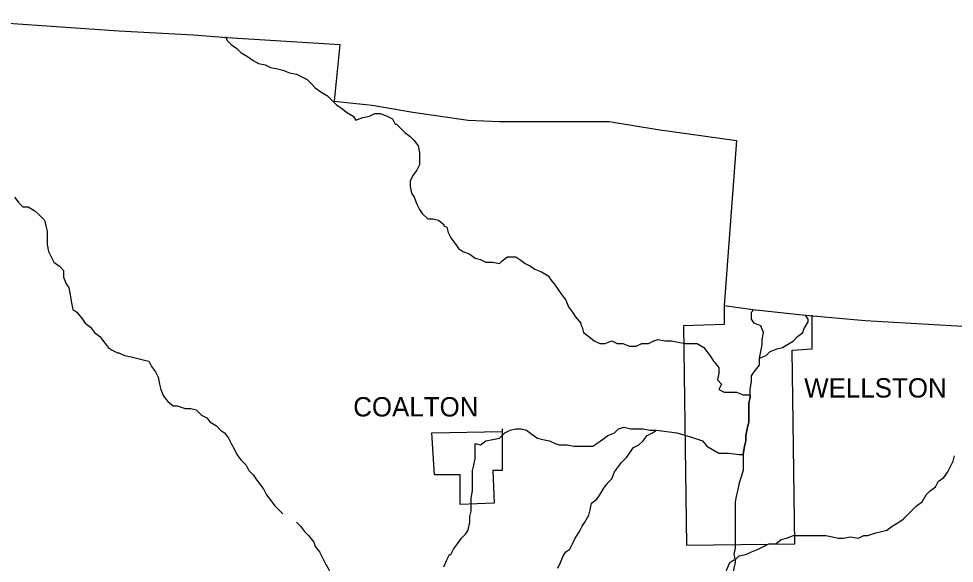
# Model space of a CAD drawing. Extents: x 0 to 34, y 0 to 22.
# Drawn here: x 6.966 to 7.908, y 18.061 to 18.609 of the extents above; entities that cross this region are included whole.
import ezdxf

# ---------------------------------------------------------------- set-up
doc = ezdxf.new("R2010")
doc.units = 0
doc.layers.add('Default', color=7, linetype='Continuous')

msp = doc.modelspace()

# ---------------------------------------------------------------- linework, layer by layer
at = {"layer": 'Default'}
for points in [[(6.89248, 18.60931), (7.067, 18.59704), (7.14199, 18.59295), (7.17607, 18.59022), (7.28924, 18.58341), (7.28378, 18.52614), (7.32196, 18.52205), (7.36286, 18.51524), (7.41876, 18.50705), (7.45012, 18.50569), (7.50738, 18.50569), (7.56056, 18.50569), (7.60964, 18.49751), (7.68872, 18.4866), (7.67645, 18.32027)], [(7.17607, 18.59022), (7.17471, 18.59022), (7.17607, 18.5875), (7.18016, 18.58341), (7.18562, 18.57932), (7.18971, 18.57523), (7.19652, 18.57114), (7.20198, 18.56705), (7.20743, 18.56432), (7.21425, 18.56295), (7.2197, 18.56023), (7.22652, 18.55886), (7.23197, 18.5575), (7.23879, 18.55477), (7.24561, 18.55341), (7.25106, 18.55068), (7.25651, 18.54796), (7.2606, 18.54387), (7.26469, 18.53978), (7.27015, 18.53569), (7.27697, 18.5316), (7.28106, 18.52751), (7.28651, 18.52205), (7.2906, 18.51933), (7.29605, 18.51524), (7.30287, 18.51114), (7.3056, 18.50705), (7.31241, 18.50978), (7.31923, 18.51114), (7.32468, 18.51387), (7.33014, 18.51387), (7.33696, 18.51114), (7.34241, 18.50842), (7.34514, 18.50296)], [(7.34514, 18.50296), (7.3465, 18.50296), (7.3465, 18.50296), (7.35059, 18.49887), (7.35468, 18.49478), (7.36013, 18.49069), (7.36422, 18.4866), (7.36831, 18.48115), (7.36968, 18.47433), (7.36968, 18.46888), (7.36968, 18.46206), (7.36695, 18.45661), (7.36286, 18.45115), (7.36013, 18.4457), (7.36013, 18.44025), (7.3615, 18.43343), (7.36422, 18.42934), (7.36695, 18.42252), (7.36968, 18.41707), (7.3724, 18.41298), (7.37786, 18.40752), (7.38331, 18.40752), (7.38877, 18.40616), (7.39422, 18.40207)], [(6.96201, 18.42934), (6.96611, 18.42389), (6.9702, 18.4198), (6.97565, 18.4198), (6.97565, 18.4198)], [(6.97565, 18.4198), (6.98247, 18.41571), (6.98656, 18.41162), (6.99201, 18.40616), (6.99337, 18.40071), (6.99474, 18.39525), (6.99474, 18.38844), (6.99474, 18.38162), (6.9961, 18.3748), (6.99883, 18.36935), (7.00155, 18.3639), (7.00701, 18.35981), (7.0111, 18.35571), (7.0111, 18.3489), (7.01382, 18.34208), (7.01655, 18.33799), (7.01792, 18.33117), (7.01928, 18.32299), (7.02064, 18.31618), (7.02473, 18.31345), (7.03019, 18.30663), (7.03291, 18.30254), (7.03837, 18.29845), (7.04246, 18.293), (7.04791, 18.28891), (7.052, 18.28345), (7.05609, 18.278), (7.06018, 18.27527), (7.06563, 18.27255), (7.06563, 18.27255), (7.067, 18.27255)], [(7.39422, 18.40207), (7.39422, 18.40071), (7.39422, 18.40071), (7.39695, 18.39934), (7.39831, 18.39389), (7.40104, 18.38844), (7.40513, 18.38298), (7.40922, 18.37753), (7.41331, 18.3748), (7.42012, 18.37208), (7.42558, 18.36799), (7.43103, 18.36662), (7.43649, 18.3639), (7.4433, 18.3639), (7.45012, 18.36253), (7.45285, 18.36526), (7.4583, 18.36935), (7.46648, 18.36935), (7.47057, 18.36662), (7.47602, 18.36253), (7.48148, 18.35981), (7.48557, 18.35708), (7.49239, 18.35435), (7.4992, 18.35026), (7.50193, 18.34617), (7.50602, 18.34072), (7.50875, 18.33663), (7.51284, 18.33117), (7.51693, 18.32572), (7.51965, 18.3189), (7.52374, 18.31345), (7.52647, 18.30936), (7.53192, 18.30254)], [(7.67645, 18.32027), (7.67645, 18.30118), (7.63554, 18.29981), (7.63827, 18.07894), (7.74735, 18.0803), (7.74462, 18.27527), (7.76507, 18.27664), (7.76507, 18.31072)], [(7.67645, 18.32027), (7.70508, 18.31618), (7.75825, 18.31072), (7.81824, 18.30527), (7.95731, 18.29709), (8.08411, 18.29163)], [(7.7119, 18.26709), (7.71326, 18.27391), (7.71462, 18.28073), (7.71462, 18.28618), (7.71599, 18.293), (7.71326, 18.29981), (7.70644, 18.30254), (7.70372, 18.30663), (7.70372, 18.31345), (7.70508, 18.31481), (7.70508, 18.31618)], [(7.7119, 18.26709), (7.71871, 18.26982), (7.7228, 18.27391), (7.72962, 18.27664), (7.73507, 18.278), (7.74189, 18.28209), (7.74598, 18.28482), (7.75007, 18.28891), (7.75553, 18.293), (7.75689, 18.29709), (7.76098, 18.3039), (7.76098, 18.30663), (7.75825, 18.31072)], [(7.53192, 18.30254), (7.53192, 18.30118), (7.53329, 18.29845), (7.53465, 18.293), (7.54011, 18.28891), (7.54556, 18.28482), (7.55101, 18.28209), (7.55647, 18.28209), (7.56328, 18.28482), (7.56874, 18.28209), (7.57419, 18.28209), (7.58101, 18.27936), (7.58783, 18.27936), (7.59328, 18.28209), (7.6001, 18.28209), (7.60555, 18.28482), (7.60964, 18.28618), (7.61646, 18.28482), (7.62327, 18.28482), (7.63009, 18.28345), (7.63691, 18.28209), (7.64373, 18.28209), (7.64918, 18.28209), (7.656, 18.278), (7.65872, 18.27391), (7.66281, 18.26846), (7.66554, 18.26437)], [(7.067, 18.27255), (7.07245, 18.26982), (7.07927, 18.26846), (7.08472, 18.26709), (7.09154, 18.26573), (7.09699, 18.26437), (7.09972, 18.25891), (7.10381, 18.25346), (7.10654, 18.248), (7.1079, 18.24119), (7.10926, 18.23573), (7.11199, 18.22892), (7.11608, 18.22346), (7.12154, 18.21937), (7.12563, 18.21937), (7.13381, 18.21665), (7.13926, 18.21665), (7.14471, 18.21528), (7.15017, 18.20983), (7.15562, 18.2071), (7.15835, 18.20301), (7.16516, 18.19892), (7.16925, 18.19483), (7.17335, 18.1921)], [(7.66554, 18.26437), (7.6669, 18.263), (7.67099, 18.25755), (7.67099, 18.25209), (7.66963, 18.24528), (7.67372, 18.24119), (7.67099, 18.23573), (7.67645, 18.23301), (7.6819, 18.23301), (7.68872, 18.23301), (7.69554, 18.23028), (7.70235, 18.23028)], [(7.70235, 18.23028), (7.70235, 18.23573), (7.70372, 18.24391), (7.70372, 18.24937), (7.70644, 18.25346), (7.7119, 18.26028), (7.7119, 18.26573), (7.7119, 18.26709), (7.7119, 18.26709)], [(7.69554, 18.17029), (7.6969, 18.17847), (7.69826, 18.18392), (7.69826, 18.18938), (7.69963, 18.19619), (7.70099, 18.20301), (7.70099, 18.20847), (7.70099, 18.21528), (7.70099, 18.2221), (7.70235, 18.22755), (7.70235, 18.23028)], [(7.70235, 18.23028), (7.70235, 18.22755), (7.70099, 18.2221), (7.70099, 18.21528), (7.70099, 18.20847), (7.70099, 18.20301), (7.69963, 18.19619), (7.69826, 18.18938), (7.69826, 18.18392), (7.6969, 18.17847), (7.69554, 18.17029)], [(7.51147, 18.17983), (7.51829, 18.17983), (7.52511, 18.17847), (7.53192, 18.17847), (7.53874, 18.17847), (7.5442, 18.17847), (7.54829, 18.1812), (7.55374, 18.18529), (7.55919, 18.18938), (7.56601, 18.1921), (7.5701, 18.19619), (7.57555, 18.19756), (7.58237, 18.19619), (7.58919, 18.19619), (7.59464, 18.19619), (7.60146, 18.19483), (7.60828, 18.19483), (7.60828, 18.19483)], [(7.17335, 18.1921), (7.17744, 18.18665), (7.18016, 18.1812), (7.18289, 18.17574), (7.18562, 18.17029), (7.18971, 18.16484), (7.19516, 18.15938), (7.19789, 18.15393), (7.20198, 18.14984), (7.2047, 18.14575), (7.20879, 18.14029), (7.21288, 18.13484), (7.21561, 18.12939), (7.22106, 18.12257), (7.22379, 18.11848), (7.22925, 18.11303), (7.23197, 18.1103), (7.23197, 18.1103)], [(7.45285, 18.19619), (7.45285, 18.15393), (7.4433, 18.15393), (7.44467, 18.12121), (7.41058, 18.11984), (7.41058, 18.14984), (7.38468, 18.14984), (7.38195, 18.1921), (7.45285, 18.19347)], [(7.42558, 18.1812), (7.43103, 18.17983), (7.43649, 18.18392), (7.4433, 18.18529), (7.45012, 18.18665), (7.45557, 18.1921), (7.46103, 18.19483), (7.46648, 18.19619), (7.47193, 18.19619), (7.47739, 18.19483), (7.48284, 18.19074), (7.4883, 18.18665), (7.49375, 18.18529), (7.50057, 18.18392), (7.50602, 18.1812), (7.51011, 18.17983), (7.51147, 18.17983)], [(7.5142, 18.06803), (7.51693, 18.07212), (7.52102, 18.07485), (7.52374, 18.0803), (7.52647, 18.08576), (7.53056, 18.09257), (7.53329, 18.09803), (7.53602, 18.10212), (7.54011, 18.10894), (7.54147, 18.11439), (7.54283, 18.12121), (7.54829, 18.1253), (7.55101, 18.12939), (7.5551, 18.1362), (7.55919, 18.14166), (7.56328, 18.14575), (7.56601, 18.15257), (7.5701, 18.15802), (7.57283, 18.16211), (7.57828, 18.16756), (7.58101, 18.17165), (7.5851, 18.17711), (7.59055, 18.17983), (7.59464, 18.18392), (7.59873, 18.18938), (7.60419, 18.1921), (7.60828, 18.19483), (7.60828, 18.19483)], [(7.60828, 18.19483), (7.62873, 18.1921), (7.64236, 18.18801), (7.65463, 18.18392), (7.65872, 18.17847), (7.67099, 18.17165), (7.68054, 18.17165), (7.69145, 18.17029), (7.69554, 18.17029)], [(7.40104, 18.0694), (7.40376, 18.07485), (7.40785, 18.0803), (7.41194, 18.08576), (7.41603, 18.08985), (7.41876, 18.09394), (7.42012, 18.10212), (7.42012, 18.10757), (7.42149, 18.11303), (7.42149, 18.11984), (7.42149, 18.12666), (7.42285, 18.13348), (7.42285, 18.14029), (7.42285, 18.14575), (7.42285, 18.15393), (7.42421, 18.15938), (7.42558, 18.1662), (7.42558, 18.17165), (7.42558, 18.17847), (7.42558, 18.17983), (7.42558, 18.1812)], [(7.69554, 18.17029), (7.69554, 18.1662), (7.69554, 18.15938), (7.69554, 18.15393), (7.69281, 18.14575), (7.69145, 18.14166), (7.69008, 18.13484), (7.68872, 18.12939), (7.68735, 18.12257), (7.68735, 18.11712), (7.68735, 18.10894), (7.68735, 18.10212), (7.68735, 18.0953), (7.68735, 18.08985), (7.68735, 18.08303), (7.68735, 18.07621), (7.68599, 18.0694), (7.68735, 18.06394)], [(7.80325, 18.08712), (7.81143, 18.08576), (7.81688, 18.08848), (7.82097, 18.08848), (7.82915, 18.09121), (7.8346, 18.09257), (7.84006, 18.09394), (7.84551, 18.09803), (7.85233, 18.10212), (7.85642, 18.10485), (7.86187, 18.1103), (7.86733, 18.11575), (7.87005, 18.11848), (7.87551, 18.12257), (7.8796, 18.12939), (7.88369, 18.13348), (7.88914, 18.13757), (7.89187, 18.14302), (7.89732, 18.14711), (7.90141, 18.15257), (7.90414, 18.15802), (7.90687, 18.16347), (7.90823, 18.16893)], [(7.24561, 18.10212), (7.2497, 18.09803), (7.25379, 18.09257), (7.25788, 18.08848), (7.26333, 18.08167), (7.26469, 18.07758), (7.26878, 18.07212), (7.27151, 18.06667), (7.27424, 18.06122), (7.27833, 18.0544), (7.27969, 18.04895), (7.28378, 18.04349), (7.28651, 18.03667), (7.28787, 18.03122), (7.29196, 18.02577), (7.29469, 18.02031), (7.29742, 18.01486), (7.30014, 18.00804), (7.30014, 18.00668), (7.30287, 18.00532), (7.30287, 18.00532)], [(7.68735, 18.06394), (7.69145, 18.06803), (7.69826, 18.0694), (7.70372, 18.07212), (7.71053, 18.07485), (7.71599, 18.07758), (7.72144, 18.0803), (7.72826, 18.0803), (7.73371, 18.08439), (7.73916, 18.08576), (7.74598, 18.08848), (7.75144, 18.08848), (7.75689, 18.08848), (7.76507, 18.08848), (7.77189, 18.08848), (7.7787, 18.08848), (7.78552, 18.08712), (7.79097, 18.08576), (7.79643, 18.08576), (7.80325, 18.08712), (7.80325, 18.08712)], [(7.39422, 18.05713), (7.39695, 18.06394), (7.39967, 18.0694), (7.40104, 18.0694), (7.40104, 18.0694)], [(7.50875, 18.05576), (7.51147, 18.06122), (7.5142, 18.06803), (7.5142, 18.06803), (7.5142, 18.06803)], [(7.67372, 18.03122), (7.67372, 18.03667), (7.67645, 18.04349), (7.67781, 18.04895), (7.67917, 18.0544), (7.6819, 18.06122), (7.68599, 18.06394), (7.68735, 18.06394)], [(7.68735, 18.06394), (7.68735, 18.06122), (7.68599, 18.05576), (7.68463, 18.04895), (7.68463, 18.04349), (7.68463, 18.03667), (7.68326, 18.02986)]]:
    msp.add_lwpolyline(points, dxfattribs=at)

# ---------------------------------------------------------------- texts
for s, p in [('WELLSTON', (7.75689, 18.22755)), ('COALTON', (7.30287, 18.20847))]:
    msp.add_text(s, height=0.019502, dxfattribs=at).set_placement(p)

doc.saveas('drawing.dxf')
